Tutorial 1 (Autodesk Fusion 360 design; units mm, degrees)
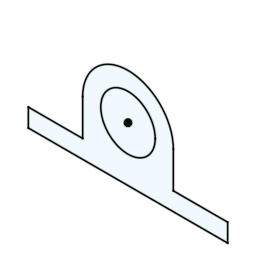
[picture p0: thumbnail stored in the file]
sketch "Sketch1" plane through (0, 0, 0) normal (0, 1, 0) x axis (1, 0, 0)
  line L1 (-50, 40) -> (-50, 0)
  line L2 (-110, 40) -> (-50, 40)
  line L3 (-110, 60) -> (-110, 40)
  line L4 (110, 60) -> (-110, 60)
  line L5 (110, 40) -> (110, 60)
  line L6 (50, 40) -> (110, 40)
  line L7 (50, 0) -> (50, 40)
  circle C1 centre (0, 0) radius 30
  arc A1 centre (0, 0) radius 50 clockwise from (50, 0) to (-50, 0)
  point P1 (0, 0)
  point P2 (0, 0)
  point P3 (0, 0)
  point P8 (-110, 60)
  point P9 (110, 60)
  point P7 (-110, 40)
  coincident P1 P2
  coincident P2 P3
  tangent A1 L1
  vertical L1
  perpendicular L1 L2
  perpendicular L2 L3
  perpendicular L3 L4
  perpendicular L4 L5
  perpendicular L3 L6
  tangent A1 L7
  equal L3 L5
  equal L2 L6
  equal L1 L7
  dimension "d1" diameter C1 = 60
  dimension "d2" distance P2 L4 = 60
  dimension "d3" distance P8 P9 = 220
  dimension "d4" radius A1 = 50
  dimension "d5" distance P7 P8 = 20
